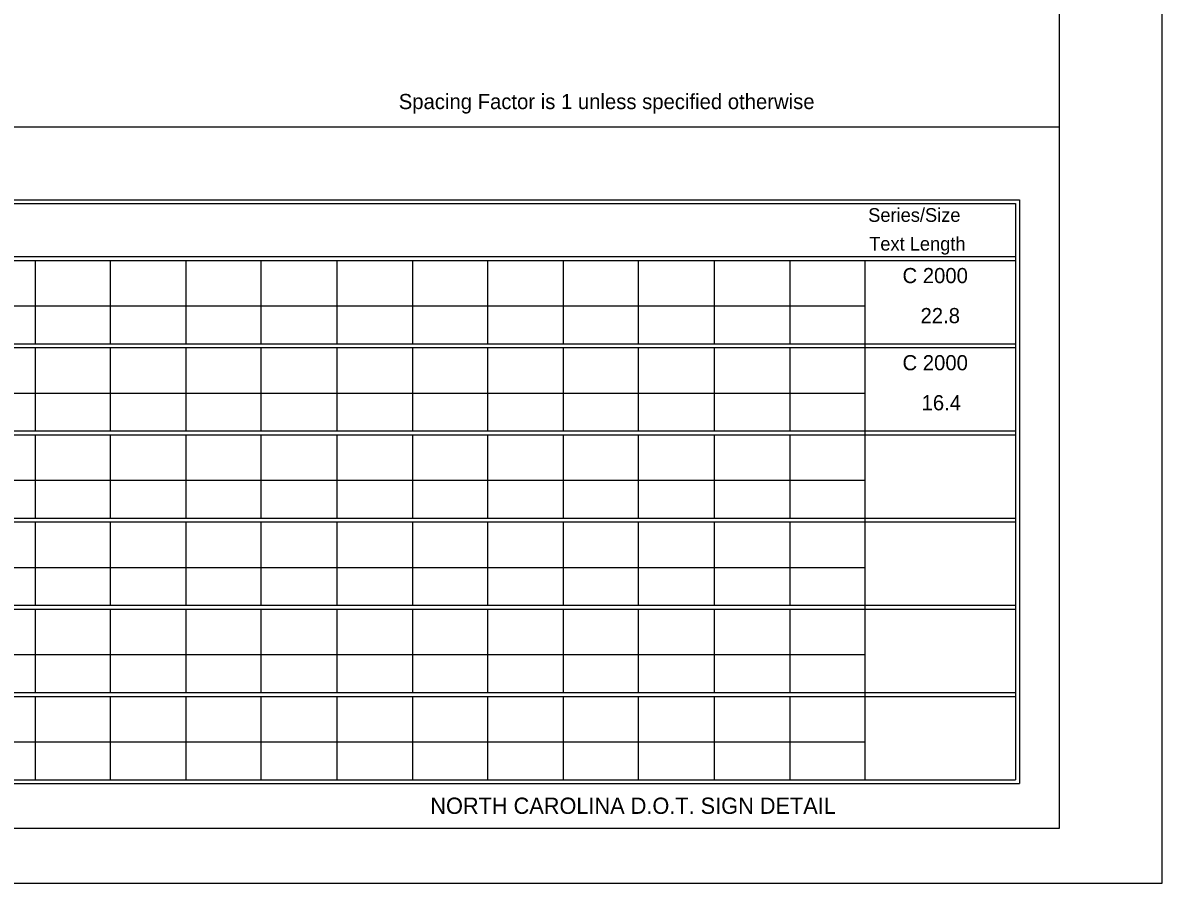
# Model space of a CAD drawing. Extents: x 1788.1 to 1851.2, y 237.2 to 283.4.
# Drawn here: x 1837.39 to 1851.19, y 262.55 to 272.98 of the extents above; entities that cross this region are included whole.
import ezdxf

# ---------------------------------------------------------------- set-up
doc = ezdxf.new("R2010")
doc.units = 0
doc.layers.add('Old_Level_2', color=7, linetype='Continuous')
doc.layers.add('Sheet Plot Border Outside CELL', color=7, linetype='Continuous')

msp = doc.modelspace()

# ---------------------------------------------------------------- linework, layer by layer
at = {"layer": 'Old_Level_2'}
for p, q in [((1832.78, 271.718), (1849.944, 271.718)), ((1821.981, 270.146), (1843.759, 270.146)), ((1821.981, 270.1), (1843.759, 270.1)), ((1837.536, 270.1), (1837.536, 269.089)), ((1838.444, 270.1), (1838.444, 269.089)), ((1839.363, 270.1), (1839.363, 269.089)), ((1840.272, 270.1), (1840.272, 269.089)), ((1841.19, 270.1), (1841.19, 269.089)), ((1842.108, 270.1), (1842.108, 269.089)), ((1842.785, 270.146), (1849.417, 270.146)), ((1842.785, 270.1), (1849.417, 270.1)), ((1843.017, 270.1), (1843.017, 269.089)), ((1843.017, 270.1), (1843.017, 269.089)), ((1843.935, 270.1), (1843.935, 269.089)), ((1844.844, 270.1), (1844.844, 269.089)), ((1845.763, 270.1), (1845.763, 269.089)), ((1846.681, 270.1), (1846.681, 269.089)), ((1847.59, 270.1), (1847.59, 263.975)), ((1822.9, 269.548), (1843.759, 269.548)), ((1842.785, 269.548), (1847.59, 269.548)), ((1847.59, 269.339), (1847.59, 269.089)), ((1821.981, 269.089), (1843.759, 269.089)), ((1821.981, 269.043), (1843.759, 269.043)), ((1837.536, 269.043), (1837.536, 268.033)), ((1838.444, 269.043), (1838.444, 268.033)), ((1839.363, 269.043), (1839.363, 268.033)), ((1840.272, 269.043), (1840.272, 268.033)), ((1841.19, 269.043), (1841.19, 268.033)), ((1842.108, 269.043), (1842.108, 268.033)), ((1842.785, 269.089), (1849.417, 269.089)), ((1842.785, 269.043), (1849.417, 269.043)), ((1843.017, 269.043), (1843.017, 268.033)), ((1843.017, 269.043), (1843.017, 268.033)), ((1843.935, 269.043), (1843.935, 268.033)), ((1844.844, 269.043), (1844.844, 268.033)), ((1845.763, 269.043), (1845.763, 268.033)), ((1846.681, 269.043), (1846.681, 268.033)), ((1847.59, 269.043), (1847.59, 268.564)), ((1822.9, 268.492), (1843.759, 268.492)), ((1842.785, 268.492), (1847.59, 268.492)), ((1847.59, 268.362), (1847.59, 268.033)), ((1821.981, 268.033), (1843.759, 268.033)), ((1842.785, 268.033), (1849.417, 268.033)), ((1821.981, 267.987), (1843.759, 267.987)), ((1837.536, 267.987), (1837.536, 266.976)), ((1838.444, 267.987), (1838.444, 266.976)), ((1839.363, 267.987), (1839.363, 266.976)), ((1840.272, 267.987), (1840.272, 266.976)), ((1841.19, 267.987), (1841.19, 266.976)), ((1842.108, 267.987), (1842.108, 266.976)), ((1842.785, 267.987), (1849.417, 267.987)), ((1843.017, 267.987), (1843.017, 266.976)), ((1843.017, 267.987), (1843.017, 266.976)), ((1843.935, 267.987), (1843.935, 266.976)), ((1844.844, 267.987), (1844.844, 266.976)), ((1845.763, 267.987), (1845.763, 266.976)), ((1846.681, 267.987), (1846.681, 266.976)), ((1847.59, 267.987), (1847.59, 267.576)), ((1822.9, 267.436), (1843.759, 267.436)), ((1842.785, 267.436), (1847.59, 267.436)), ((1847.59, 267.274), (1847.59, 266.976)), ((1821.981, 266.976), (1843.759, 266.976)), ((1821.981, 266.93), (1843.759, 266.93)), ((1837.536, 266.93), (1837.536, 265.92)), ((1838.444, 266.93), (1838.444, 265.92)), ((1839.363, 266.93), (1839.363, 265.92)), ((1840.272, 266.93), (1840.272, 265.92)), ((1841.19, 266.93), (1841.19, 265.92)), ((1842.108, 266.93), (1842.108, 265.92)), ((1842.785, 266.976), (1849.417, 266.976)), ((1842.785, 266.93), (1849.417, 266.93)), ((1843.017, 266.93), (1843.017, 265.92)), ((1843.017, 266.93), (1843.017, 265.92)), ((1843.935, 266.93), (1843.935, 265.92)), ((1844.844, 266.93), (1844.844, 265.92)), ((1845.763, 266.93), (1845.763, 265.92)), ((1846.681, 266.93), (1846.681, 265.92)), ((1847.59, 266.93), (1847.59, 266.488)), ((1822.9, 266.379), (1843.759, 266.379)), ((1842.785, 266.379), (1847.59, 266.379)), ((1847.59, 266.185), (1847.59, 265.92)), ((1837.536, 266.037), (1837.536, 265.92)), ((1838.444, 266.037), (1838.444, 265.92)), ((1839.363, 266.037), (1839.363, 265.92)), ((1840.272, 266.037), (1840.272, 265.92)), ((1841.19, 266.037), (1841.19, 265.92)), ((1842.108, 266.037), (1842.108, 265.92)), ((1843.017, 266.037), (1843.017, 265.92)), ((1843.017, 266.037), (1843.017, 265.92)), ((1843.935, 266.037), (1843.935, 265.92)), ((1844.844, 266.037), (1844.844, 265.92)), ((1845.763, 266.037), (1845.763, 265.92)), ((1846.681, 266.037), (1846.681, 265.92)), ((1847.59, 266.037), (1847.59, 265.92)), ((1821.981, 265.92), (1843.759, 265.92)), ((1821.981, 265.92), (1843.759, 265.92)), ((1821.981, 265.874), (1843.759, 265.874)), ((1821.981, 265.874), (1843.759, 265.874)), ((1837.536, 265.874), (1837.536, 264.929)), ((1837.536, 265.874), (1837.536, 264.863)), ((1838.444, 265.874), (1838.444, 264.929)), ((1838.444, 265.874), (1838.444, 264.863)), ((1839.363, 265.874), (1839.363, 264.929)), ((1839.363, 265.874), (1839.363, 264.863)), ((1840.272, 265.874), (1840.272, 264.929)), ((1840.272, 265.874), (1840.272, 264.863)), ((1841.19, 265.874), (1841.19, 264.929)), ((1841.19, 265.874), (1841.19, 264.863)), ((1842.108, 265.874), (1842.108, 264.929)), ((1842.108, 265.874), (1842.108, 264.863)), ((1842.785, 265.92), (1849.417, 265.92)), ((1842.785, 265.92), (1849.417, 265.92)), ((1842.785, 265.874), (1849.417, 265.874)), ((1842.785, 265.874), (1849.417, 265.874)), ((1843.017, 265.874), (1843.017, 264.929)), ((1843.017, 265.874), (1843.017, 264.863)), ((1843.017, 265.874), (1843.017, 264.929)), ((1843.017, 265.874), (1843.017, 264.863)), ((1843.935, 265.874), (1843.935, 264.929)), ((1843.935, 265.874), (1843.935, 264.863)), ((1844.844, 265.874), (1844.844, 264.929)), ((1844.844, 265.874), (1844.844, 264.863)), ((1845.763, 265.874), (1845.763, 264.929)), ((1845.763, 265.874), (1845.763, 264.863)), ((1846.681, 265.874), (1846.681, 264.929)), ((1846.681, 265.874), (1846.681, 264.863)), ((1847.59, 265.874), (1847.59, 265.419)), ((1847.59, 265.874), (1847.59, 265.419)), ((1822.9, 265.323), (1843.759, 265.323)), ((1822.9, 265.323), (1843.759, 265.323)), ((1842.785, 265.323), (1847.59, 265.323)), ((1842.785, 265.323), (1847.352, 265.323)), ((1847.59, 265.157), (1847.59, 264.929)), ((1847.59, 265.157), (1847.59, 264.863)), ((1837.536, 264.981), (1837.536, 264.863)), ((1838.444, 264.981), (1838.444, 264.863)), ((1839.363, 264.981), (1839.363, 264.863)), ((1840.272, 264.981), (1840.272, 264.863)), ((1841.19, 264.981), (1841.19, 264.863)), ((1842.108, 264.981), (1842.108, 264.863)), ((1843.017, 264.981), (1843.017, 264.863)), ((1843.017, 264.981), (1843.017, 264.863)), ((1843.935, 264.981), (1843.935, 264.863)), ((1844.844, 264.981), (1844.844, 264.863)), ((1845.763, 264.981), (1845.763, 264.863)), ((1846.681, 264.981), (1846.681, 264.863)), ((1847.59, 264.981), (1847.59, 264.863)), ((1821.981, 264.863), (1843.759, 264.863)), ((1821.981, 264.863), (1843.759, 264.863)), ((1842.785, 264.863), (1849.417, 264.863)), ((1842.785, 264.863), (1849.417, 264.863)), ((1821.981, 264.817), (1843.759, 264.817)), ((1821.981, 264.817), (1843.759, 264.817)), ((1837.536, 264.817), (1837.536, 263.807)), ((1837.536, 264.817), (1837.536, 263.807)), ((1838.444, 264.817), (1838.444, 263.807)), ((1838.444, 264.817), (1838.444, 263.807)), ((1839.363, 264.817), (1839.363, 263.807)), ((1839.363, 264.817), (1839.363, 263.807)), ((1840.272, 264.817), (1840.272, 263.807)), ((1840.272, 264.817), (1840.272, 263.807)), ((1841.19, 264.817), (1841.19, 263.807)), ((1841.19, 264.817), (1841.19, 263.807)), ((1842.108, 264.817), (1842.108, 263.807)), ((1842.108, 264.817), (1842.108, 263.807)), ((1842.785, 264.817), (1849.417, 264.817)), ((1842.785, 264.817), (1849.417, 264.817)), ((1843.017, 264.817), (1843.017, 263.807)), ((1843.017, 264.817), (1843.017, 263.807)), ((1843.017, 264.817), (1843.017, 263.807)), ((1843.017, 264.817), (1843.017, 263.807)), ((1843.935, 264.817), (1843.935, 263.807)), ((1843.935, 264.817), (1843.935, 263.807)), ((1844.844, 264.817), (1844.844, 263.807)), ((1844.844, 264.817), (1844.844, 263.807)), ((1845.763, 264.817), (1845.763, 263.807)), ((1845.763, 264.817), (1845.763, 263.807)), ((1846.681, 264.817), (1846.681, 263.807)), ((1846.681, 264.817), (1846.681, 263.807)), ((1847.59, 264.817), (1847.59, 264.392)), ((1847.59, 264.817), (1847.59, 264.392)), ((1822.9, 264.266), (1843.759, 264.266)), ((1822.9, 264.266), (1843.759, 264.266)), ((1842.785, 264.266), (1847.59, 264.266)), ((1842.785, 264.266), (1847.414, 264.266)), ((1847.59, 264.07), (1847.59, 263.807)), ((1847.59, 264.07), (1847.59, 263.807)), ((1821.934, 263.761), (1843.759, 263.761)), ((1821.981, 263.807), (1843.759, 263.807)), ((1821.981, 263.807), (1843.759, 263.807)), ((1821.981, 263.761), (1843.759, 263.761)), ((1842.785, 263.807), (1849.417, 263.807)), ((1842.785, 263.807), (1849.417, 263.807)), ((1842.785, 263.761), (1849.464, 263.761)), ((1842.785, 263.761), (1849.417, 263.761))]:
    msp.add_line(p, q, dxfattribs=at)
msp.add_lwpolyline([(1821.618, 282.859), (1849.944, 282.859), (1849.944, 263.214), (1821.618, 263.214)], close=True, dxfattribs=at)
for points in [[(1821.934, 264.929), (1821.934, 270.834), (1843.759, 270.834)], [(1821.981, 264.929), (1821.981, 270.789), (1843.759, 270.789)], [(1842.785, 270.834), (1849.464, 270.834), (1849.464, 264.929)], [(1842.785, 270.789), (1849.417, 270.789), (1849.417, 264.929)], [(1849.417, 266.037), (1849.417, 263.807)], [(1849.464, 266.037), (1849.464, 263.761)]]:
    msp.add_lwpolyline(points, dxfattribs=at)
at = {"layer": 'Sheet Plot Border Outside CELL'}
msp.add_lwpolyline([(1851.194, 283.406), (1821.023, 283.406), (1821.023, 262.552), (1851.194, 262.552)], close=True, dxfattribs=at)

# ---------------------------------------------------------------- texts
at = {"layer": 'Old_Level_2'}
for s, height, p in [('Spacing Factor is 1 unless specified otherwise', 0.18373, (1841.942, 271.933)), ('Series/Size', 0.16535, (1847.631, 270.567)), ('Text Length', 0.16535, (1847.643, 270.219)), ('NORTH CAROLINA D.O.T. SIGN DETAIL', 0.19685, (1842.325, 263.393))]:
    msp.add_text(s, height=height, rotation=360, dxfattribs=at).set_placement(p)
for s, p in [('C 2000', (1848.047, 269.824)), ('22.8', (1848.265, 269.339)), ('C 2000', (1848.047, 268.768)), ('16.4', (1848.278, 268.283))]:
    msp.add_text(s, height=0.1837, dxfattribs=at).set_placement(p)

doc.saveas('drawing.dxf')
